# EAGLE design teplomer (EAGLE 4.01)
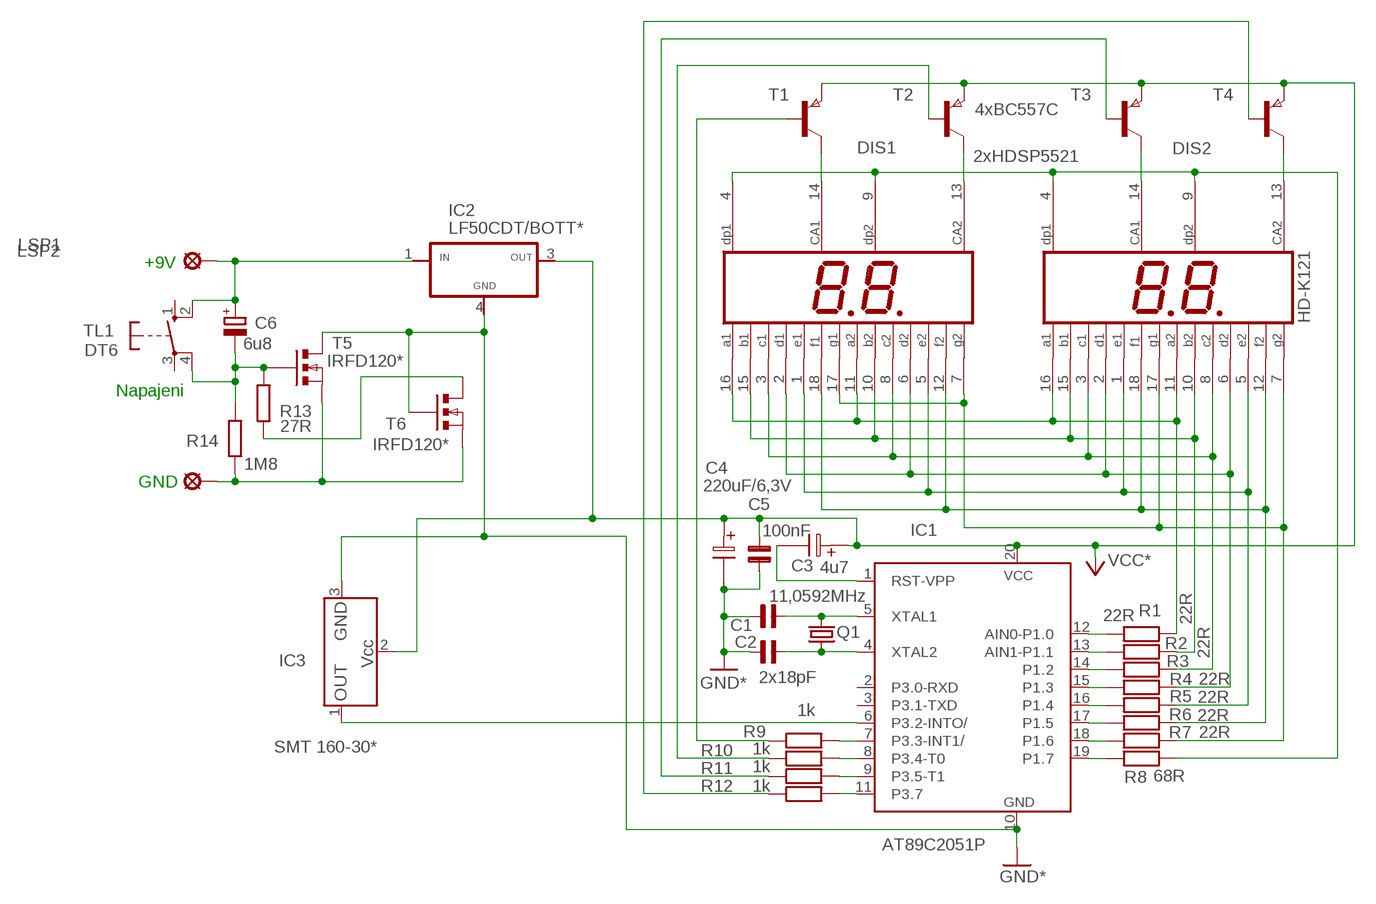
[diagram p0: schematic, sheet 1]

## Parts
C1  2x18pF  C5/3  [C5B3]
C2  C5/3  [C5B3]
C3  4u7  CT04  [CT04]
C4  220uF/6,3V  E5X11  [E50]
C5  100nF  C5/3  [C5B3]
C6  6u8  CPOL-EUE5-4  [E5-4]
DIS1  2xHDSP5521  HD-K121  [HDSP-R]
DIS2  HD-K121  [HDSP-R]
IC1  AT89C2051P  [DIL20]
IC2  LF50CDT/BOTT*  LF50CTD/BOTT*  [DPAK_BOT]
IC3  SMT 160-30*  [TO-92C]
LSP1  LSP10  [LSP10]
LSP2  LSP10  [LSP10]
Q1  11,0592MHz  HC49U-V  [HC49U-V]
R1  22R  RR  [RR]
R2  22R  RR  [RR]
R3  22R  RR  [RR]
R4  22R  RR  [RR]
R5  22R  RR  [RR]
R6  22R  RR  [RR]
R7  22R  RR  [RR]
R8  68R  RR  [RR]
R9  1k  RR  [RR]
R10  1k  RR  [RR]
R11  1k  RR  [RR]
R12  1k  RR  [RR]
R13  27R  R-EU_0207/10  [0207/10]
R14  1M8  R-EU_0207/10  [0207/10]
T1  4xBC557C  BC557C  [TO-92C]
T2  BC557C  [TO-92C]
T3  BC557C  [TO-92C]
T4  BC557C  [TO-92C]
T5  IRFD120*  [DIL04]
T6  IRFD120*  [DIL04]
TL1  DT6  [DT6]

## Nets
GND: C1.1 C2.1 C4.2 C5.1 IC1.10(GND) IC2.4(GND) IC3.3 T5.3(D) T6.1(G) ; supply symbol labelled GND*
N$1: C1.2 IC1.5(XTAL1) Q1.2
N$2: C2.2 IC1.4(XTAL2) Q1.1
N$3: IC1.12(AIN0-P1.0) R1.1
N$4: IC1.13(AIN1-P1.1) R2.1
N$5: DIS1.11(A2) DIS1.16(A1) DIS2.11(A2) DIS2.16(A1) R1.2
N$6: IC1.14(P1.2) R3.1
N$7: IC1.15(P1.3) R4.1
N$8: DIS1.10(B2) DIS1.15(B1) DIS2.10(B2) DIS2.15(B1) R2.2
N$9: IC1.16(P1.4) R5.1
N$10: DIS1.3(C1) DIS1.8(C2) DIS2.3(C1) DIS2.8(C2) R3.2
N$11: IC1.17(P1.5) R6.1
N$12: DIS1.2(D1) DIS1.6(D2) DIS2.2(D1) DIS2.6(D2) R4.2
N$13: IC1.18(P1.6) R7.1
N$14: DIS1.1(E1) DIS1.5(E2) DIS2.1(E1) DIS2.5(E2) R5.2
N$15: IC1.19(P1.7) R8.1
N$16: DIS1.12(F2) DIS1.18(F1) DIS2.12(F2) DIS2.18(F1) R6.2
N$17: IC1.7(P3.3-INT1/) R9.2
N$18: DIS1.7(G2) DIS1.17(G1) DIS2.7(G2) DIS2.17(G1) R7.2
N$19: IC1.8(P3.4-T0) R10.2
N$20: DIS1.4(DP1) DIS1.9(DP2) DIS2.4(DP1) DIS2.9(DP2) R8.2
N$21: IC1.9(P3.5-T1) R11.2
N$22: IC1.11(P3.7) R12.2
N$23: DIS1.14(CA1) T1.3(C)
N$24: DIS1.13(CA2) T2.3(C)
N$25: DIS2.14(CA1) T3.3(C)
N$26: DIS2.13(CA2) T4.3(C)
N$28: R11.1 T3.2(B)
N$29: R9.1 T1.2(B)
N$30: R10.1 T2.2(B)
N$31: R12.1 T4.2(B)
N$32: C6.+ IC2.1(IN) LSP1.MP TL1.2
N$33: C3.2 IC1.1(RST-VPP)
N$34: IC1.6(P3.2-INTO/) IC3.1
N$35: LSP2.MP R14.1 T5.2(S) T6.2(S)
N$36: C6.- R13.1 R14.2 T5.1(G) TL1.4
N$37: R13.2 T6.3(D)
VCC: C3.1 C4.1 C5.2 IC1.20(VCC) IC2.3(OUT) IC3.2 T1.1(E) T2.1(E) T3.1(E) T4.1(E) ; supply symbol labelled VCC*
Unconnected: IC1.2(P3.0-RXD) IC1.3(P3.1-TXD) TL1.1 TL1.3

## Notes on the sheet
- +9V
- Napajeni
- GND

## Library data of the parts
C1 C2 C5 = capacitor-wima:C: CAPACITOR
C3 = GM99:CT04
C4 = GM99:E5X11
C6 = rcl:CPOL-EU: POLARIZED CAPACITOR, European symbol
DIS1 DIS2 = display-hp:HD-K121: LED DISPLAY 2 x 1 character 7 segment, decimal points right
IC1 = atmel:AT89C2051: 80C31 MICROCONTROLLER 2 Kbytes FLASH 2.7 V
IC2 = LF50CDT:LF50CTD/BOTT
IC3 = DH_servis:SMT 160-30
LSP1 LSP2 = solpad:LSP10: SOLDER PAD
Q1 = crystal:HC49U-V: CRYSTAL
R1-R12 = GM99:RR
R13 R14 = rcl:R-EU_: RESISTOR, European symbol
T1-T4 = GM99:BC557C
T5 T6 = DH_servis:IRFD120
TL1 = switch-misc:DT6: ITT SWITCH

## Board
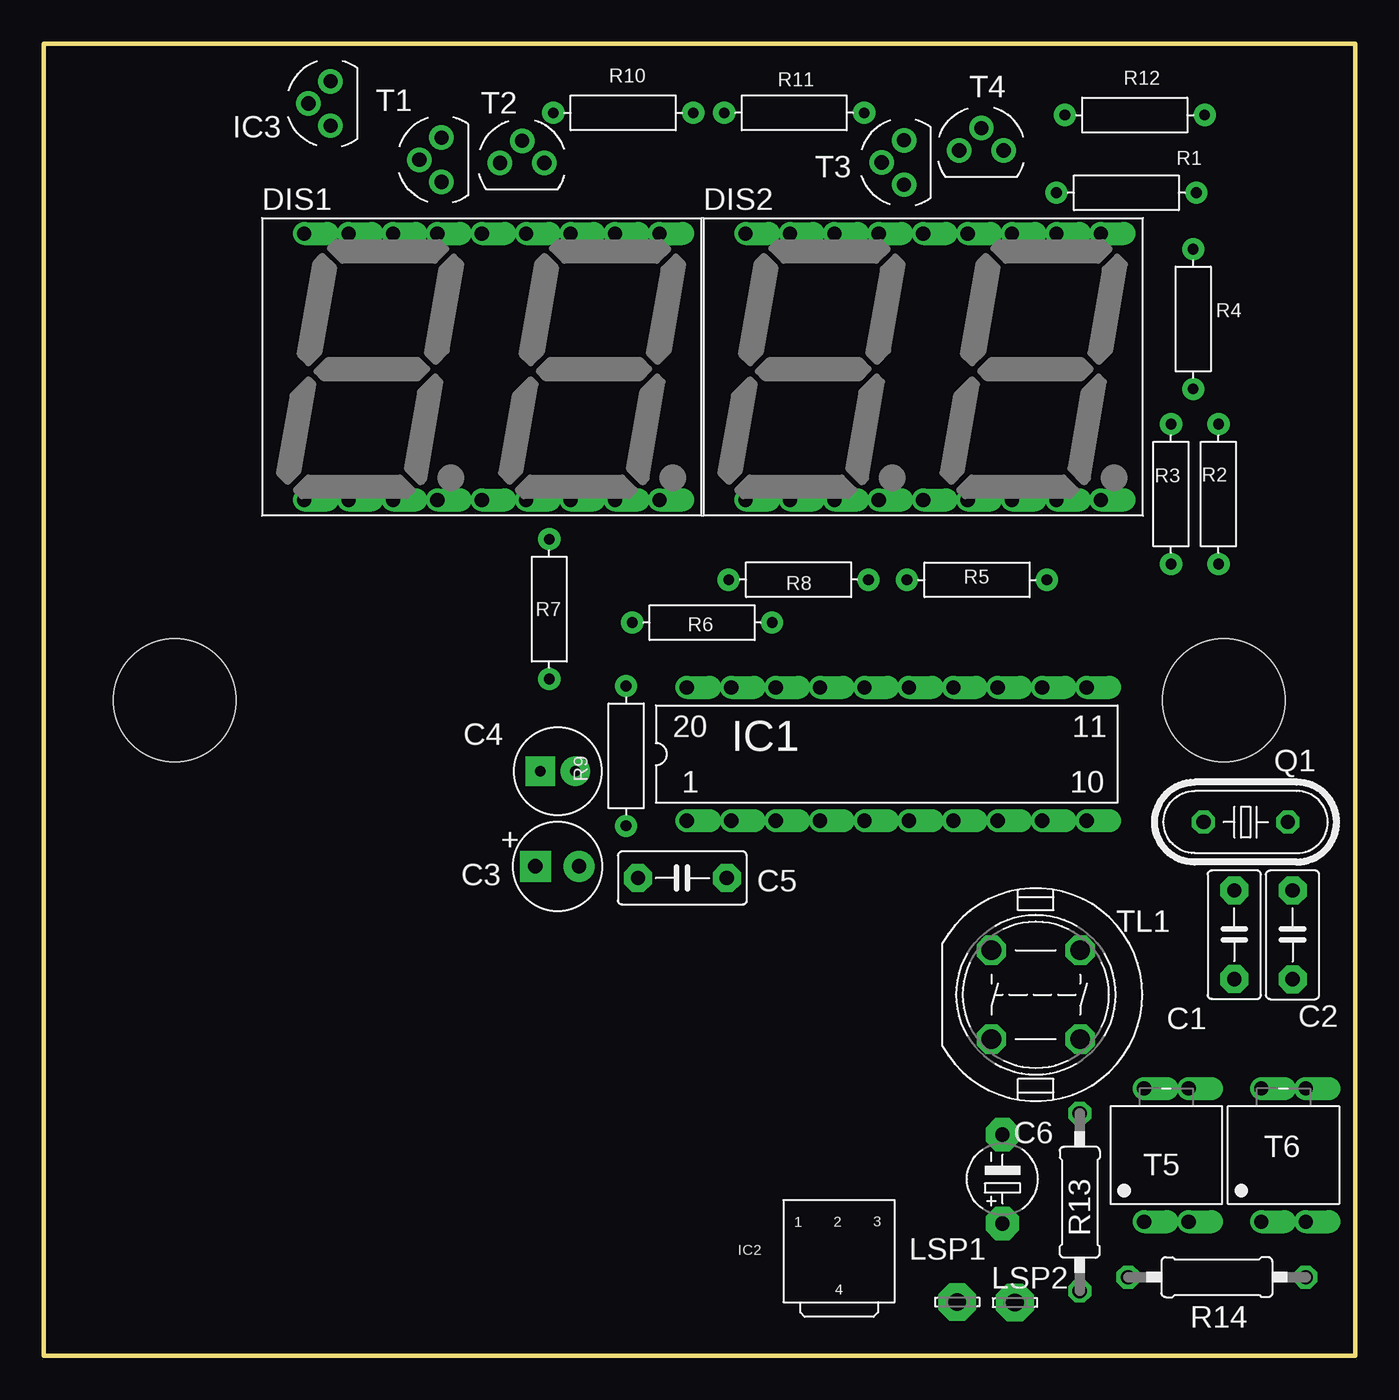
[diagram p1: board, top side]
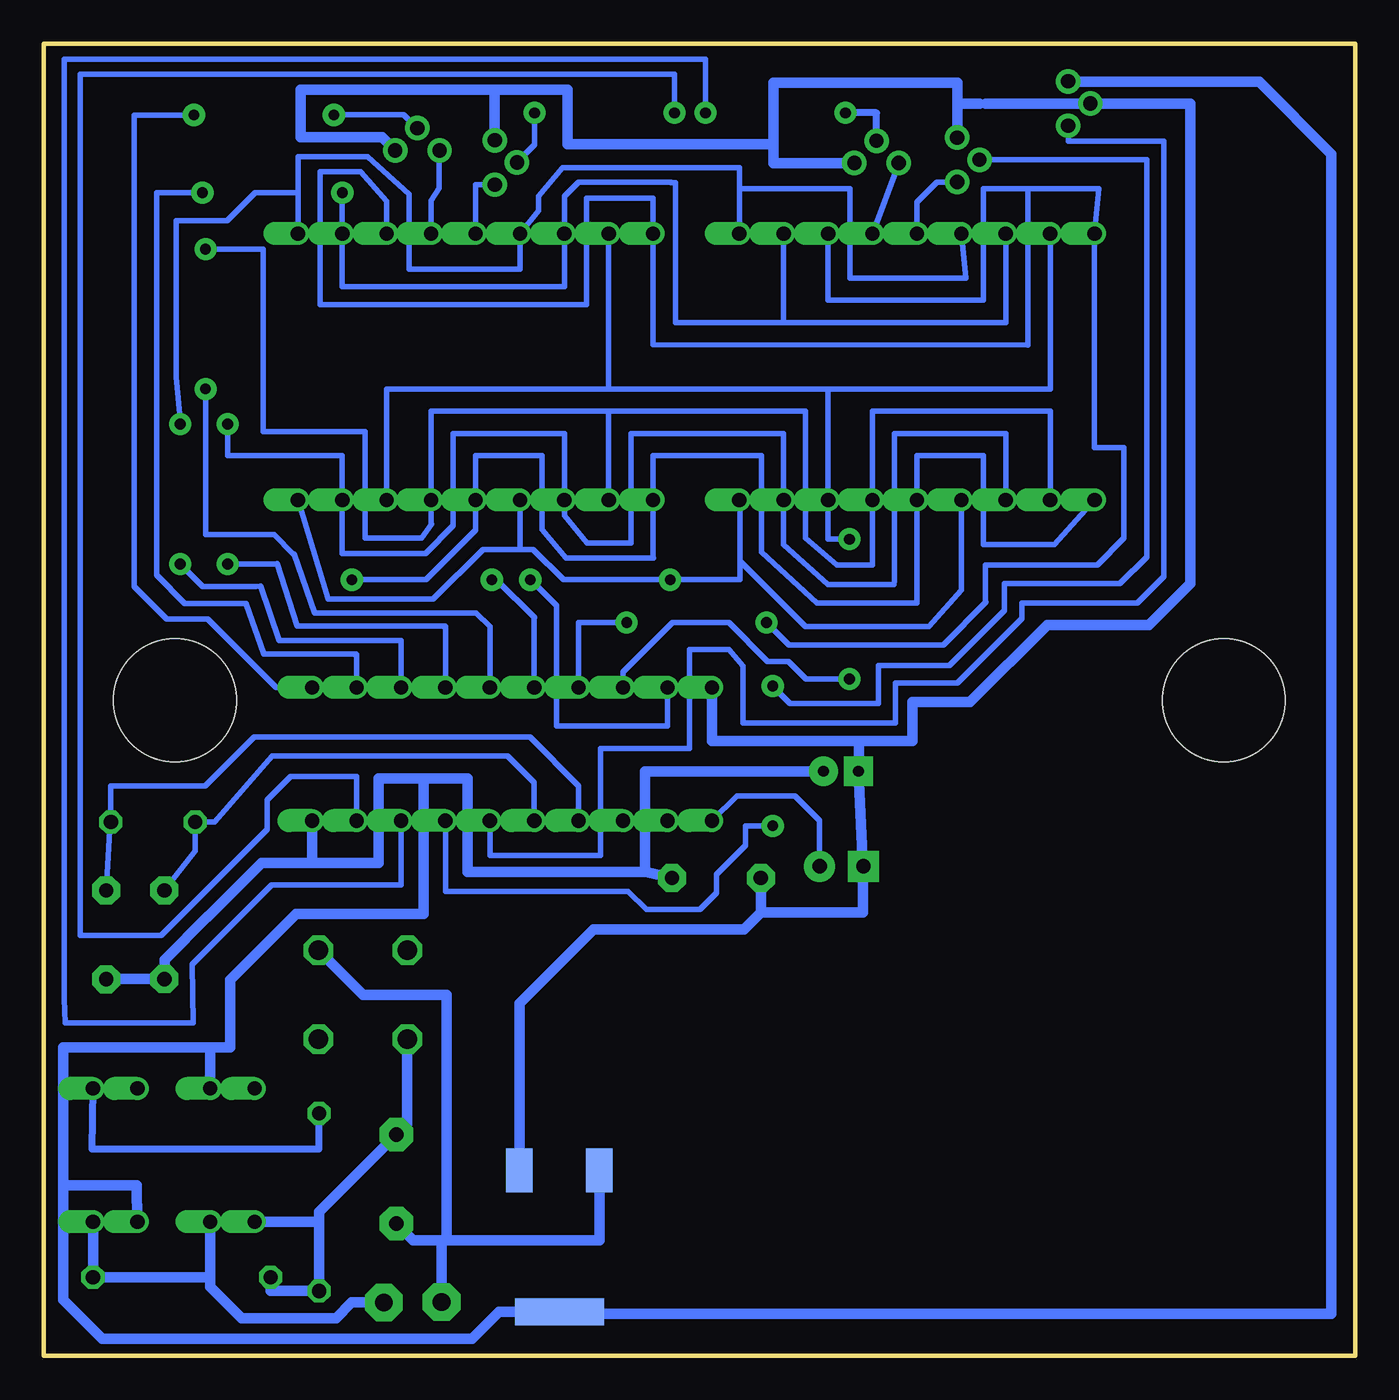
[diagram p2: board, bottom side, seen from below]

Size 75.01 x 75.05 mm. Coordinates in mm from the lower left corner, seen from the top.
Outline: 0,0 0,25 0,75.05 75,75.05 75,0 49.93,0 0,0
Copper layers used: Bottom
Holes 7 mm at 67.5,37.5 7.5,37.5

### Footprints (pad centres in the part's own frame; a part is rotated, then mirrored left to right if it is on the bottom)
C5B3 = drill 0.813 pad 1.6 octagon: 1 -2.54,0; 2 2.54,0
CT04 = drill 0.813 pad 1.778 square: 1 0,0 | drill 0.813 pad 1.778 round: 2 2.5,0
E50 = drill 0.61 pad 1.676 square: 1 0,0 | drill 0.61 pad 1.676 round: 2 2,0
E5-4 = drill 0.813 pad 1.905 octagon: + -2.54,0; - 2.54,0
HDSP-R = drill 0.813 offset: 1 -10.16,-7.62; 2 -7.62,-7.62; 3 -5.08,-7.62; 4 -2.54,-7.62; 5 0,-7.62; 6 2.54,-7.62; 7 5.08,-7.62; 8 7.62,-7.62; 9 10.16,-7.62; 10 10.16,7.62; 11 7.62,7.62; 12 5.08,7.62; 13 2.54,7.62; 14 0,7.62; 15 -2.54,7.62; 16 -5.08,7.62; 17 -7.62,7.62; 18 -10.16,7.62
DIL20 = drill 0.813 offset: 1 -11.43,-3.81; 2 -8.89,-3.81; 3 -6.35,-3.81; 4 -3.81,-3.81; 5 -1.27,-3.81; 6 1.27,-3.81; 7 3.81,-3.81; 8 6.35,-3.81; 9 8.89,-3.81; 10 11.43,-3.81; 11 11.43,3.81; 12 8.89,3.81; 13 6.35,3.81; 14 3.81,3.81; 15 1.27,3.81; 16 -1.27,3.81; 17 -3.81,3.81; 18 -6.35,3.81; 19 -8.89,3.81; 20 -11.43,3.81
DPAK_BOT = smd 1.524 x 2.54 bottom: 1 5.52,-1.64; 3 0.95,-1.64 | smd 5.08 x 1.524 bottom: 4 3.251,6.452
TO-92C = drill 0.813 pad 1.397 round: 1 0,2.54; 2 1.27,1.27; 3 0,0
LSP10 = drill 1.016 pad 2.159 octagon: MP 0,0
HC49U-V = drill 0.813 octagon: 1 -2.413,0; 2 2.413,0
RR = drill 0.61 pad 1.27 round: 1 0,0; 2 8,0
0207/10 = drill 0.813 octagon: 1 -5.08,0; 2 5.08,0
TO-92C' = drill 0.813 pad 1.397 round: 1 0,0; 2 1.27,1.27; 3 0,2.54
DIL04 = drill 0.813 offset: 1 -1.27,-3.81; 2 1.27,-3.81; 3 1.27,3.81; 4 -1.27,3.81
DT6 = drill 1.118 octagon: 1 -2.54,2.54; 2 2.54,2.54; 3 2.54,-2.54; 4 -2.54,-2.54

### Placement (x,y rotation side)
C1  68.1,24.08 90 top
C2  71.43,24.08 90 top
C3  28.12,28 0 top
C4  28.41,33.43 0 top
C5  36.53,27.33 180 top
C6  54.84,10.11 90 top
DIS1  25.06,56.57 0 top
DIS2  50.31,56.57 0 top
IC1  48.22,34.42 0 top
IC2  48.74,8.97 180 top
IC3  16.41,72.9 180 top
LSP1  52.25,3.07 0 top
LSP2  55.55,3.05 0 top
Q1  68.75,30.53 180 top
R1  65.93,66.52 180 top
R2  67.2,45.29 90 top
R3  64.48,45.29 90 top
R4  65.75,55.3 90 top
R5  49.38,44.39 0 top
R6  41.66,41.94 180 top
R7  28.92,38.71 90 top
R8  47.17,44.39 180 top
R9  33.31,38.31 270 top
R10  29.15,71.1 0 top
R11  46.93,71.1 180 top
R12  58.41,70.97 0 top
R13  59.26,8.79 90 top
R14  67.11,4.5 180 top
T1  4xBC557C  [TO-92C']  22.75,69.68 180 top
T2  [TO-92C']  28.64,68.23 90 top
T3  [TO-92C']  49.21,69.53 180 top
T4  [TO-92C']  54.9,68.95 90 top
T5  64.21,11.48 0 top
T6  70.92,11.48 0 top
TL1  56.75,20.66 0 top

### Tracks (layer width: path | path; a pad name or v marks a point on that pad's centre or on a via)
GND
  Bottom 0.305: C1.1 | 71.45,21.54 | 71.45,21.54 C2.1 | 71.45,21.55 71.45,21.54 | 65.63,25.09 65.63,25.12
  Bottom 0.406: 55.85,33.02 53.31,33.02 | C4.2 | IC2.4 45.11,2.52 45.11,2.36 | 40.62,27.69 40.69,27.69 40.69,27.71
  Bottom 0.61: 59.65,28.19 IC1.10 | 59.65,28.19 55.85,28.19 55.85,33.02 53.29,33.02 | 53.29,33.02 50.75,33.02 50.75,27.69 40.69,27.69 | 40.62,27.69 40.62,33.43 C4.2 | 59.65,28.19 62.53,28.19 65.63,25.09 | C1.1 71.45,21.55 | C1.1 68.1,22.66 65.63,25.12 | 40.69,27.71 C5.1 | 45.49,2.49 45.47,2.49 | 45.49,2.49 IC2.4 48.95,2.52 50.49,0.96 71.65,0.96 73.89,3.2 73.89,9.58 | 45.49,2.49 45.52,2.49 45.52,2.41 1.35,2.41 1.35,68.73 5.49,72.87 16.41,72.87 IC3.3 | 73.89,9.58 73.89,9.75 70.56,9.75 | 70.56,9.75 70.38,9.75 | T6.1 69.7,9.75 70.56,9.75 | T5.3 65.48,17.65 73.89,17.65 | 73.89,9.58 73.89,17.65 | 73.89,17.65 64.34,17.65 64.34,21.49 60.55,25.27 53.29,25.27 53.29,33.02 | 53.29,33.02 52.09,33.02
N$1
  Bottom 0.305: C1.2 66.34,28.89 Q1.2 | Q1.2 | Q1.2 65.23,30.53 61.95,34.31 48.47,34.31 46.95,32.8 IC1.5
N$2
  Bottom 0.305: C2.2 71.17,31.01 Q1.1 71.16,32.59 65.76,32.59 62.97,35.38 62.26,35.38 | 62.26,35.38 62.31,35.38 | 62.26,35.38 47.19,35.38 44.41,32.6 IC1.4
N$3
  Bottom 0.305: R1.1 68.56,66.52 68.56,44.66 66.93,43.03 63.42,43.03 63.42,43 62.43,40.16 62.43,40.13 57.12,40.13 | 57.12,40.13 57.15,40.11 | 57.12,40.11 57.23,40.11 | 57.12,40.11 57.12,40.13 | IC1.12 57.11,40.11 57.12,40.11
N$4
  Bottom 0.305: IC1.13 54.56,38.23 54.56,40.92 61.54,40.92 62.59,44.02 62.89,43.99 65.9,43.99 R2.1
N$5
  Bottom 0.305: DIS1.16 19.98,59.11 32.68,59.11 | 32.68,59.11 DIS1.11 | 32.68,59.11 38.88,59.11 38.88,67.11 39.12,67.11 39.12,67.13 44.43,67.13 45.23,66.33 DIS2.16 45.23,61.14 57.93,61.14 DIS2.11 57.93,66.22 57.91,66.22 | 57.91,66.22 57.91,65.99 | R1.2 57.91,66.52 57.91,66.22
N$6
  Bottom 0.305: 52.05,41.71 52.12,41.71 | 52.05,41.71 52.05,41.73 60.5,41.73 61.65,45.31 61.82,45.29 R3.1 | IC1.14 52.03,41.71 52.05,41.71
N$7
  Bottom 0.305: 65.75,48.58 R4.1 | IC1.15 49.49,41.72 50.27,42.49 51.77,42.49 | 51.77,42.49 51.72,42.49 | 51.77,42.49 59.51,42.49 60.68,45.85 60.73,45.87 61.82,46.97 65.75,46.97 65.75,48.58 | 65.75,48.58 65.75,48.53
N$8
  Bottom 0.305: DIS1.15 22.26,61.65 28.89,61.65 28.89,66.75 29.63,66.76 35.22,66.76 | 60.47,66.52 60.47,68.57 56.49,68.57 54.1,66.44 54.1,62.17 | 35.22,66.76 35.22,67.96 45.34,67.96 46.71,66.34 46.71,65.5 DIS2.15 47.77,62.16 54.1,62.16 54.1,62.17 | 35.22,66.76 34.97,66.75 | 35.22,66.76 DIS1.10 | 35.22,66.76 | 60.47,66.52 DIS2.10 | 60.47,66.52 62.92,66.52 64.52,64.92 67.44,64.92 67.44,55.98 67.18,53.26 R2.2 | 54.1,62.17 54.1,62.23
N$9
  Bottom 0.305: R5.1 49.11,44.39 46.94,42.22 46.94,42.24 46.95,42.23 IC1.16
N$10
  Bottom 0.254: DIS1.8 32.67,48.95 32.66,48.95 32.69,48.92
  Bottom 0.305: DIS1.3 19.98,52.76 26.35,52.76 26.35,44.38 26.36,44.12 30.15,44.12 32.69,46.41 32.69,48.92 | DIS1.8 32.68,52.76 41.42,52.76 41.42,46.97 41.42,46.5 43.92,46.5 45.23,48.06 DIS2.3 45.23,52.76 51.58,52.76 51.58,47.48 53.16,45.9 57.92,45.9 | R3.2 64.48,51.49 57.93,51.49 DIS2.8 | 57.92,45.9 57.93,46.47 DIS2.8 | 57.92,45.9 57.92,45.94 | DIS2.8 57.92,48.97
N$11
  Bottom 0.305: IC1.17 44.42,38.23 44.42,41.94 R6.1
N$12
  Bottom 0.305: DIS1.2 17.44,54.03 27.6,54.03 DIS1.6 27.6,45.24 27.61,45.24 28.63,45.24 29.64,45.24 31.43,46.77 31.43,54.03 42.69,54.03 | 42.69,54.03 52.85,54.03 DIS2.6 52.85,47.57 52.83,47.57 53.39,46.76 56.62,46.76 56.62,46.78 | 42.69,54.03 DIS2.2 | R4.2 62.46,63.3 62.46,52.85 56.62,52.85 56.62,46.78 | 56.62,46.78 56.62,47.04
N$13
  Bottom 0.305: R7.1 31.4,38.71 32.41,39.73 33.6,39.73 35.81,41.94 39.04,41.94 41.86,39.12 IC1.18
N$14
  Bottom 0.305: 40.15,45.64 45.14,45.64 46.5,47.25 46.5,51.49 50.31,51.49 DIS2.5 50.31,47.23 53.14,44.4 56.92,44.4 56.92,44.39 R5.2 | 40.15,45.64 DIS2.1 40.15,51.49 33.95,51.49 33.95,45.96 30.79,43.05 25.06,43.05 DIS1.5 25.06,51.49 21.25,51.49 21.25,46.41 21,46.41 | 40.15,45.64 40.13,45.64 | 21,46.41 21.01,46.41 | DIS1.1 17.19,46.41 21,46.41
N$15
  Bottom 0.305: IC1.19 | IC1.19 | IC1.19 39.32,36.02 45.67,36.02 45.67,42.9 R8.1
N$16
  Bottom 0.305: 18.71,66.75 18.71,57.81 40.15,57.84 DIS2.18 40.15,66.22 43.96,66.22 43.96,60.12 59.2,60.12 59.2,67.67 59.18,67.67 59.18,67.72 | DIS1.12 30.14,60.38 21.25,60.38 21.25,66.75 18.71,66.75 | 18.71,66.75 14.64,66.75 DIS1.18 14.9,51.94 | 14.9,51.94 13.21,51.94 13.21,46.76 14.73,45.24 21.13,45.24 21.13,43.1 21.11,43.1 23.55,40.66 32.16,40.66 | 14.9,51.94 14.64,51.94 | DIS2.12 55.39,66.05 56.87,67.73 59.18,67.73 59.18,67.72 | 32.16,40.66 32.23,40.66 | R6.2 32.39,40.66 32.16,40.66 | 59.18,67.72 59.18,67.11
N$17
  Bottom 0.305: R9.2 34.87,30.31 34.87,29.18 36.52,27.53 36.52,26.47 37.47,25.53 40.54,25.53 41.58,26.57 52.02,26.57 52.02,30.61 IC1.7
N$18
  Bottom 0.305: DIS1.17 17.44,55.3 30.14,55.3 | 30.14,55.3 DIS1.7 30.14,46.71 R7.2 | 30.14,55.3 55.39,55.3 DIS2.7 | R7.2 28.91,46.71 | R7.2 | 30.14,55.3 30.12,55.3 | 30.14,55.3 | DIS2.17 42.69,55.3 30.14,55.3
N$19
  Bottom 0.305: R10.2 37.15,74.17 73.84,74.17 73.84,20.42 73.76,19.05 66.45,19.05 66.52,22.38 61.98,26.92 54.57,26.92 IC1.8
N$20
  Bottom 0.305: DIS1.9 35.18,48.95 35.18,45.47 | 47.77,46.13 47.02,46.13 45.28,44.39 R8.2 35.18,44.39 35.18,45.21 | 47.77,46.13 DIS2.4 | 47.77,46.13 49.88,46.13 52.73,43.28 58.75,43.28 DIS2.9 | DIS1.4 22.52,43.8 24.36,41.71 31.42,41.71 35.18,45.47 | 35.18,45.21 34.92,45.24 | 35.18,45.47 35.18,45.21
N$21
  Bottom 0.305: R11.2 38.93,73.3 72.92,73.3 72.92,24.05 68.28,24.05 62.23,30.1 62.23,31.8 60.88,33.15 57.1,33.15 57.1,30.61 IC1.9
N$22
  Bottom 0.305: R12.2 69.83,70.97 69.83,43.99 67.97,42.14 65.63,42.14 61.72,38.23 IC1.11
N$23
  Bottom 0.305: DIS1.14 25.06,65.98 23.9,67.13 T1.3 | T1.3
N$24
  Bottom 0.305: DIS1.13 27.61,64.15 T2.3
N$25
  Bottom 0.305: DIS2.14 50.29,64.19 50.29,66.98 T3.3
N$26
  Bottom 0.305: DIS2.13 52.85,66.07 52.38,66.8 52.38,68.93 T4.3
N$28
  Bottom 0.305: T3.2 46.93,69.27 R11.1
N$29
  Bottom 0.305: T1.2 11.91,68.41 11.91,45.7 13.44,44.17 20.07,44.17 20.07,42.62 23.19,39.5 27.25,39.5 27.25,37.31 32.31,37.31 R9.1
N$30
  Bottom 0.406: T2.2 | T2.2 | R10.1 27.37,71.1 T2.2
N$31
  Bottom 0.305: R12.1 58.4,70.99 54.41,70.99 53.64,70.22 T4.2
N$32
  Bottom 0.406: 43.13,10.72 43.13,10.61 IC2.1 | 51.97,6.58 51.97,6.6 51.99,6.6
  Bottom 0.61: 52.25,6.6 LSP1.MP | IC2.1 43.22,6.6 51.99,6.6 52.25,6.6 | TL1.2 56.74,20.65 51.97,20.65 51.97,6.6 | C6.+ 53.87,6.6 52.25,6.6
N$33
  Bottom 0.305: IC1.1 35.36,32.03 32.03,32.03 30.63,30.63 30.63,27.99 C3.2
N$34
  Bottom 0.305: IC1.6 49.49,28.63 43.16,28.63 43.16,34.75 38.08,34.75 38.08,40.39 35.81,40.39 35,39.45 35,36.2 26.29,36.2 26.29,38.48 22.73,38.48 19.05,42.16 19.05,43.05 12.45,43.05 10.92,44.58 10.92,69.47 15.95,69.47 | 15.95,69.47 16.38,69.47 | 15.95,69.47 16.41,69.47 IC3.1
N$35
  Bottom 0.61: LSP2.MP 57.38,3.05 58.29,2.13 63.68,2.13 65.48,3.94 65.48,4.5 | T6.2 R14.1 65.48,4.5 | 65.48,4.5 T5.2
N$36
  Bottom 0.61: 62.03,4.52 R14.2 62.03,3.71 R13.1 59.26,6.88 | 59.26,6.88 59.26,8.23 C6.- 54.21,13.28 TL1.4 | T5.1 59.26,7.67 59.26,6.88
N$37
  Bottom 0.406: T6.3 72.24,11.81 59.26,11.81 R13.2
VCC
  Bottom 0.305: 33.25,72 33.25,72.05 | 33.25,69.33 33.25,69.31 | 49.68,72.41 49.21,72.41
  Bottom 0.406: 28.4,33.43 C4.1 | C3.1 28.14,27.99 28.14,28.02 | 21.11,71.63 21.49,71.63 | 14.89,71.63 IC3.2 | 22.35,71.63 22.61,71.63 22.76,71.63 22.76,72.81 22.75,72.81
  Bottom 0.61: T1.1 22.75,72.81 33.25,72.81 33.25,72 33.25,69.33 33.25,68.23 T2.1 | 33.25,69.31 45.04,69.31 45.04,72.41 49.68,72.41 60.3,72.41 60.3,69.69 55.64,69.69 T4.1 | 49.21,72.41 T3.1 | IC1.20 36.79,35.15 28.37,35.18 | 28.37,35.18 28.4,33.43 28.14,27.99 28.14,25.35 33.98,25.35 | 28.37,35.18 25.32,35.18 25.32,37.39 22.02,37.39 17.6,41.81 11.79,41.81 9.42,44.17 9.41,71.63 14.89,71.63 21.11,71.63 | 21.49,71.63 22.61,71.63 | C5.2 | C5.2 | 33.98,25.35 C5.2 | 33.98,25.35 34.95,24.38 43.56,24.38 47.78,20.17 47.78,10.62 IC2.3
